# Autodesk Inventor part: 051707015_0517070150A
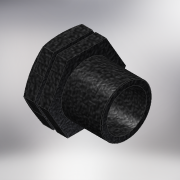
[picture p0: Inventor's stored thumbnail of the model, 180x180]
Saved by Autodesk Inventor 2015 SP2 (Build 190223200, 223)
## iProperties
Created: 2017-05
Part Number: 051707015_0517070150A
Material: Generic
Description: PLASSON PLUG 1.1/2"
Document SubType Name: Modeling
Designer: Кирилл
Density: 1 g/cm^3
Appearance: Black Cast
Author: Кирилл
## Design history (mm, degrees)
derived "051707.ipt"
feature "Solid1::051707.ipt"
tag "TaggingFeature1"
body "Solid1"
other parameters: "d1" = 47.803, "d2" = 55, "d5" = 21, "d6" = 5.57143, "d8" = 0.39, "d12" = 0, "d14" = 1.85714, "d15" = 39, "d16" = 2.22857, "d17" = 5.57143, "d19" = 0, "d21" = 3.3, "d29" = 0, "H_" = 39, "R_" = 47.803, "E_" = 55, "l_2" = 21, "d20" = 5
